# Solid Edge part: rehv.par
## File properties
Title: rehv
Author: Stella-Marii
Template: Iso Metric Part.par
Last saved by: Stella-Marii
Revision: 7
Application: Solid Edge
Density: 1050,000 kg/m^3
Accuracy: 0,990
Username: Stella-Marii
Document Number: 37
Material: Polyurethene
Face Style: Blue
Fill Style: ANSI34(Plastic)
Virtual Style: ANSI34(Plastic)
Grouping: Non-metals\Plastics
LibraryName: Materials
Coef. of Thermal Exp: 9e-05
Thermal Conductivity: 0.2
Specific Heat: 0.0
Modulus of Elasticity: 0.0
Poisson's Ratio: 0.4
Yield Stress: 0.0
Ultimate Stress: 0.0
Elongation: 0.0
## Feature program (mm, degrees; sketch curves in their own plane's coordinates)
sketch for "unnamed RevolvedProtrusion 1" plane through (0, 0, 0) normal (0, -1, 0) x-axis (1, 0, 0)
  line (70, 24) -> (70, -24)
  line (70, -24) -> (65, -24)
  line (65, -24) -> (65, -29)
  line (65, -29) -> (75, -29)
  arc centre (75, 0) radius 29 from (75, 29) to (75, -29) cw
  line (65, 29) -> (75, 29)
  line (65, 24) -> (65, 29)
  line (70, 24) -> (65, 24)
  dimension (linear) = 70
  dimension (linear) = 70
  dimension (linear) = 65
  dimension (linear) = 65
  dimension (linear) = 65
  dimension (linear) = 65
  dimension (linear) = 70
revolve "unnamed RevolvedProtrusion 1" add finite 360 deg
thinwall "unnamed Thinwall 1"
web network "WebNetwork_2"  Profile_Plane1_Distance = 74.9939 mm; Thickness = 3 mm
pattern "Pattern_1" of "WebNetwork_2" along a curve  XDirCount = 12; XDirSpacing = 34.0339 mm
web network "unnamed WebNetwork 1"
web network "unnamed WebNetwork 2"
web network "unnamed WebNetwork 3"
web network "unnamed WebNetwork 4"
web network "unnamed WebNetwork 5"
web network "unnamed WebNetwork 6"
web network "unnamed WebNetwork 7"
web network "unnamed WebNetwork 8"
web network "unnamed WebNetwork 9"
web network "unnamed WebNetwork 10"
web network "unnamed WebNetwork 11"
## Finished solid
Body 1: solid body, 223 faces, 628 edges, 432 vertices.
  Faces by surface: plane 184, torus 37, cylinder 2
  Edges by curve: line 384, intersection 168, circle 52, curve on surface 24
Bounding box of the edges (mm; curved faces can reach further): 197.976 x 197.976 x 58.000, from (-98.9882, -98.9882, -29) to (98.9882, 98.9882, 29).
Cylindrical faces by radius (mm): R65 x2
Toroidal faces (ring radius, tube radius in mm): R75 r24 x36, R75 r29 x1
Planar faces by outward normal: +x 7, +y 7, +z 2, -x 7, -y 7, -z 2, oblique 152
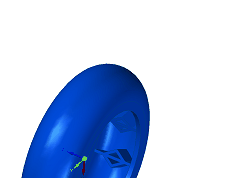
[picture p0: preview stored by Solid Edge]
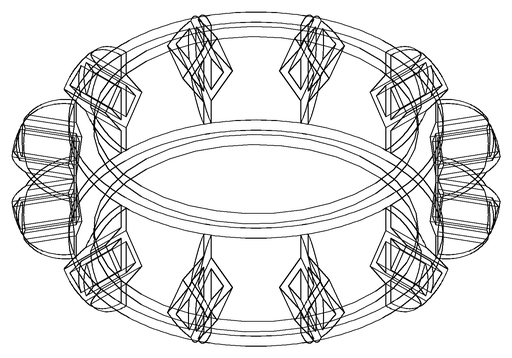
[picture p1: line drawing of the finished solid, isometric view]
